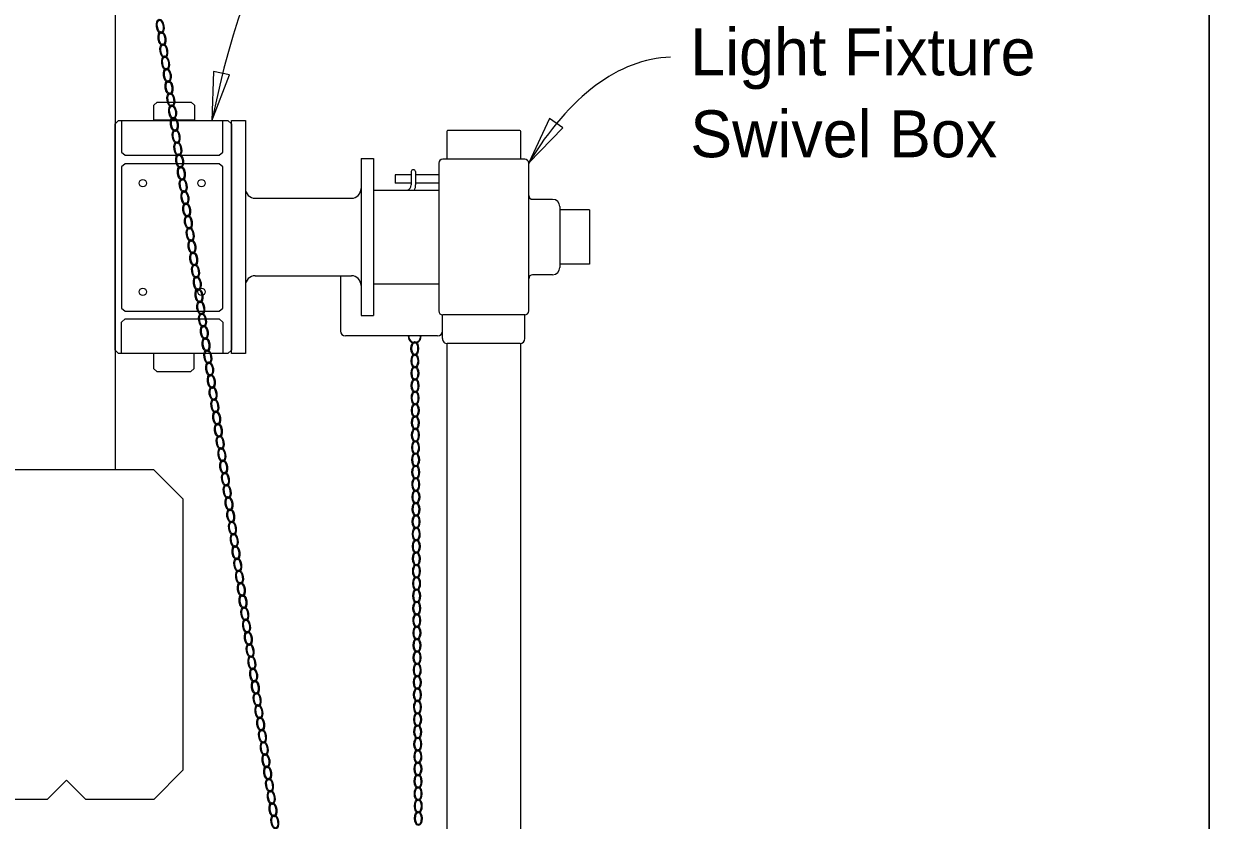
# Model space of a CAD drawing. Extents: x 0 to 20.5, y 0 to 13.
# Drawn here: x 17.979 to 20.525, y 4.722 to 6.433 of the extents above; entities that cross this region are included whole.
import ezdxf

# ---------------------------------------------------------------- set-up
doc = ezdxf.new("R2010")
doc.units = 0
for name, color, linetype in [('ActivePts-ConstElements', 7, 'Continuous'), ('Dimension', 7, 'Continuous'), ('Miscellaneous', 7, 'Continuous'), ('Miscellaneous1', 7, 'Continuous'), ('NavLight', 7, 'Continuous'), ('SupstrConc', 7, 'Continuous'), ('TrafBarrierConc', 7, 'Continuous')]:
    doc.layers.add(name, color=color, linetype=linetype)

msp = doc.modelspace()

# ---------------------------------------------------------------- linework, layer by layer
at = {"layer": 'ActivePts-ConstElements'}
msp.add_lwpolyline([(0, 0), (20.5253, 0), (20.5253, 12.9731), (0, 12.9731)], close=True, dxfattribs=at)
at = {"layer": 'Dimension'}
for points in [[(18.3832, 6.2248), (18.4208, 6.3235), (18.3862, 6.3304)], [(19.0635, 6.1339), (19.1371, 6.2096), (19.1081, 6.2296)]]:
    msp.add_lwpolyline(points, close=True, dxfattribs=at)
for centre, end_param in [((18.9015, 5.6333), 4.215808), ((19.4166, 5.0805), 3.730412)]:
    msp.add_ellipse(centre, major_axis=(0.0485, -1.2809), ratio=0.439724, start_param=3.141585, end_param=end_param, dxfattribs=at)
at = {"layer": 'Miscellaneous'}
for radius, start, end in [(0.0138, 174.5178, 5.4822), (0.0125, 173.952, 6.048)]:
    msp.add_arc((18.8186, 5.761), radius, start, end, dxfattribs=at)
for centre, major_axis, ratio in [((18.2721, 6.4275), (-0.0022, 0.0152), 0.530594), ((18.2721, 6.4275), (-0.0019, 0.0131), 0.458548), ((18.2759, 6.4012), (-0.0022, 0.0152), 0.530594), ((18.2759, 6.4012), (-0.0019, 0.0131), 0.458548), ((18.2797, 6.3749), (-0.0022, 0.0152), 0.530594), ((18.2797, 6.3749), (-0.0019, 0.0131), 0.458548), ((18.2835, 6.3486), (-0.0022, 0.0152), 0.530594), ((18.2835, 6.3486), (-0.0019, 0.0131), 0.458548), ((18.2872, 6.3223), (-0.0022, 0.0152), 0.530594), ((18.2872, 6.3223), (-0.0019, 0.0131), 0.458548), ((18.291, 6.296), (-0.0022, 0.0152), 0.530594), ((18.291, 6.296), (-0.0019, 0.0131), 0.458548), ((18.2948, 6.2697), (-0.0022, 0.0152), 0.530594), ((18.2948, 6.2697), (-0.0019, 0.0131), 0.458548), ((18.2986, 6.2434), (-0.0022, 0.0152), 0.530594), ((18.2986, 6.2434), (-0.0019, 0.0131), 0.458548), ((18.3024, 6.2171), (-0.0022, 0.0152), 0.530594), ((18.3024, 6.2171), (-0.0019, 0.0131), 0.458548), ((18.3062, 6.1908), (-0.0022, 0.0152), 0.530594), ((18.3062, 6.1908), (-0.0019, 0.0131), 0.458548), ((18.3099, 6.1645), (-0.0022, 0.0152), 0.530594), ((18.3099, 6.1645), (-0.0019, 0.0131), 0.458548), ((18.3137, 6.1382), (-0.0022, 0.0152), 0.530594), ((18.3137, 6.1382), (-0.0019, 0.0131), 0.458548), ((18.3175, 6.1119), (-0.0022, 0.0152), 0.530594), ((18.3175, 6.1119), (-0.0019, 0.0131), 0.458548), ((18.3213, 6.0856), (-0.0022, 0.0152), 0.530594), ((18.3213, 6.0856), (-0.0019, 0.0131), 0.458548), ((18.3251, 6.0593), (-0.0022, 0.0152), 0.530594), ((18.3251, 6.0593), (-0.0019, 0.0131), 0.458548), ((18.3289, 6.033), (-0.0022, 0.0152), 0.530594), ((18.3289, 6.033), (-0.0019, 0.0131), 0.458548), ((18.3326, 6.0068), (-0.0022, 0.0152), 0.530594), ((18.3326, 6.0068), (-0.0019, 0.0131), 0.458548), ((18.3364, 5.9805), (-0.0022, 0.0152), 0.530594), ((18.3364, 5.9805), (-0.0019, 0.0131), 0.458548), ((18.3402, 5.9542), (-0.0022, 0.0152), 0.530594), ((18.3402, 5.9542), (-0.0019, 0.0131), 0.458548), ((18.344, 5.9279), (-0.0022, 0.0152), 0.530594), ((18.344, 5.9279), (-0.0019, 0.0131), 0.458548), ((18.3478, 5.9016), (-0.0022, 0.0152), 0.530594), ((18.3478, 5.9016), (-0.0019, 0.0131), 0.458548), ((18.3516, 5.8753), (-0.0022, 0.0152), 0.530594), ((18.3516, 5.8753), (-0.0019, 0.0131), 0.458548), ((18.3553, 5.849), (-0.0022, 0.0152), 0.530594), ((18.3553, 5.849), (-0.0019, 0.0131), 0.458548), ((18.3591, 5.8227), (-0.0022, 0.0152), 0.530594), ((18.3591, 5.8227), (-0.0019, 0.0131), 0.458548), ((18.3629, 5.7964), (-0.0022, 0.0152), 0.530594), ((18.3629, 5.7964), (-0.0019, 0.0131), 0.458548), ((18.3667, 5.7701), (-0.0022, 0.0152), 0.530594), ((18.3667, 5.7701), (-0.0019, 0.0131), 0.458548), ((18.3705, 5.7438), (-0.0022, 0.0152), 0.530594), ((18.3705, 5.7438), (-0.0019, 0.0131), 0.458548), ((18.3743, 5.7175), (-0.0022, 0.0152), 0.530594), ((18.3743, 5.7175), (-0.0019, 0.0131), 0.458548), ((18.8188, 5.7352), (-0.0001, 0.0153), 0.530594), ((18.8188, 5.7352), (-0.0001, 0.0133), 0.458548), ((18.3781, 5.6912), (-0.0022, 0.0152), 0.530594), ((18.3781, 5.6912), (-0.0019, 0.0131), 0.458548), ((18.819, 5.7086), (-0.0001, 0.0153), 0.530594), ((18.819, 5.7086), (-0.0001, 0.0133), 0.458548), ((18.3818, 5.6649), (-0.0022, 0.0152), 0.530594), ((18.8192, 5.6821), (-0.0001, 0.0153), 0.530594), ((18.8192, 5.6821), (-0.0001, 0.0133), 0.458548), ((18.3818, 5.6649), (-0.0019, 0.0131), 0.458548), ((18.3856, 5.6386), (-0.0022, 0.0152), 0.530594), ((18.8194, 5.6555), (-0.0001, 0.0153), 0.530594), ((18.8194, 5.6555), (-0.0001, 0.0133), 0.458548), ((18.3856, 5.6386), (-0.0019, 0.0131), 0.458548), ((18.3894, 5.6123), (-0.0022, 0.0152), 0.530594), ((18.8196, 5.629), (-0.0001, 0.0153), 0.530594), ((18.8196, 5.629), (-0.0001, 0.0133), 0.458548), ((18.3894, 5.6123), (-0.0019, 0.0131), 0.458548), ((18.8198, 5.6024), (-0.0001, 0.0153), 0.530594), ((18.8198, 5.6024), (-0.0001, 0.0133), 0.458548), ((18.3932, 5.586), (-0.0022, 0.0152), 0.530594), ((18.3932, 5.586), (-0.0019, 0.0131), 0.458548), ((18.82, 5.5758), (-0.0001, 0.0153), 0.530594), ((18.82, 5.5758), (-0.0001, 0.0133), 0.458548), ((18.397, 5.5597), (-0.0022, 0.0152), 0.530594), ((18.397, 5.5597), (-0.0019, 0.0131), 0.458548), ((18.8202, 5.5493), (-0.0001, 0.0153), 0.530594), ((18.8202, 5.5493), (-0.0001, 0.0133), 0.458548), ((18.4008, 5.5334), (-0.0022, 0.0152), 0.530594), ((18.4008, 5.5334), (-0.0019, 0.0131), 0.458548), ((18.8204, 5.5227), (-0.0001, 0.0153), 0.530594), ((18.8204, 5.5227), (-0.0001, 0.0133), 0.458548), ((18.4045, 5.5071), (-0.0022, 0.0152), 0.530594), ((18.4045, 5.5071), (-0.0019, 0.0131), 0.458548), ((18.8206, 5.4961), (-0.0001, 0.0153), 0.530594), ((18.8206, 5.4961), (-0.0001, 0.0133), 0.458548), ((18.4083, 5.4808), (-0.0022, 0.0152), 0.530594), ((18.4083, 5.4808), (-0.0019, 0.0131), 0.458548), ((18.8208, 5.4696), (-0.0001, 0.0153), 0.530594), ((18.8208, 5.4696), (-0.0001, 0.0133), 0.458548), ((18.4121, 5.4545), (-0.0022, 0.0152), 0.530594), ((18.4121, 5.4545), (-0.0019, 0.0131), 0.458548), ((18.821, 5.443), (-0.0001, 0.0153), 0.530594), ((18.821, 5.443), (-0.0001, 0.0133), 0.458548), ((18.4159, 5.4282), (-0.0022, 0.0152), 0.530594), ((18.4159, 5.4282), (-0.0019, 0.0131), 0.458548), ((18.8212, 5.4164), (-0.0001, 0.0153), 0.530594), ((18.8212, 5.4164), (-0.0001, 0.0133), 0.458548), ((18.4197, 5.402), (-0.0022, 0.0152), 0.530594), ((18.4197, 5.402), (-0.0019, 0.0131), 0.458548), ((18.8214, 5.3899), (-0.0001, 0.0153), 0.530594), ((18.8214, 5.3899), (-0.0001, 0.0133), 0.458548), ((18.4235, 5.3757), (-0.0022, 0.0152), 0.530594), ((18.4235, 5.3757), (-0.0019, 0.0131), 0.458548), ((18.8216, 5.3633), (-0.0001, 0.0153), 0.530594), ((18.8216, 5.3633), (-0.0001, 0.0133), 0.458548), ((18.4272, 5.3494), (-0.0022, 0.0152), 0.530594), ((18.4272, 5.3494), (-0.0019, 0.0131), 0.458548), ((18.8218, 5.3367), (-0.0001, 0.0153), 0.530594), ((18.8218, 5.3367), (-0.0001, 0.0133), 0.458548), ((18.431, 5.3231), (-0.0022, 0.0152), 0.530594), ((18.431, 5.3231), (-0.0019, 0.0131), 0.458548), ((18.822, 5.3102), (-0.0001, 0.0153), 0.530594), ((18.822, 5.3102), (-0.0001, 0.0133), 0.458548), ((18.4348, 5.2968), (-0.0022, 0.0152), 0.530594), ((18.4348, 5.2968), (-0.0019, 0.0131), 0.458548), ((18.8222, 5.2836), (-0.0001, 0.0153), 0.530594), ((18.8222, 5.2836), (-0.0001, 0.0133), 0.458548), ((18.4386, 5.2705), (-0.0022, 0.0152), 0.530594), ((18.4386, 5.2705), (-0.0019, 0.0131), 0.458548), ((18.8224, 5.257), (-0.0001, 0.0153), 0.530594), ((18.4424, 5.2442), (-0.0022, 0.0152), 0.530594), ((18.4424, 5.2442), (-0.0019, 0.0131), 0.458548), ((18.8226, 5.2305), (-0.0001, 0.0153), 0.530594), ((18.8224, 5.257), (-0.0001, 0.0133), 0.458548), ((18.4462, 5.2179), (-0.0022, 0.0152), 0.530594), ((18.4462, 5.2179), (-0.0019, 0.0131), 0.458548), ((18.8226, 5.2305), (-0.0001, 0.0133), 0.458548), ((18.4499, 5.1916), (-0.0022, 0.0152), 0.530594), ((18.4499, 5.1916), (-0.0019, 0.0131), 0.458548), ((18.8228, 5.2039), (-0.0001, 0.0153), 0.530594), ((18.8228, 5.2039), (-0.0001, 0.0133), 0.458548), ((18.4537, 5.1653), (-0.0022, 0.0152), 0.530594), ((18.4537, 5.1653), (-0.0019, 0.0131), 0.458548), ((18.823, 5.1773), (-0.0001, 0.0153), 0.530594), ((18.823, 5.1773), (-0.0001, 0.0133), 0.458548), ((18.4575, 5.139), (-0.0022, 0.0152), 0.530594), ((18.4575, 5.139), (-0.0019, 0.0131), 0.458548), ((18.8232, 5.1508), (-0.0001, 0.0153), 0.530594), ((18.8232, 5.1508), (-0.0001, 0.0133), 0.458548), ((18.4613, 5.1127), (-0.0022, 0.0152), 0.530594), ((18.4613, 5.1127), (-0.0019, 0.0131), 0.458548), ((18.8234, 5.1242), (-0.0001, 0.0153), 0.530594), ((18.8234, 5.1242), (-0.0001, 0.0133), 0.458548), ((18.4651, 5.0864), (-0.0022, 0.0152), 0.530594), ((18.4651, 5.0864), (-0.0019, 0.0131), 0.458548), ((18.8236, 5.0976), (-0.0001, 0.0153), 0.530594), ((18.8236, 5.0976), (-0.0001, 0.0133), 0.458548), ((18.4689, 5.0601), (-0.0022, 0.0152), 0.530594), ((18.4689, 5.0601), (-0.0019, 0.0131), 0.458548), ((18.8238, 5.0711), (-0.0001, 0.0153), 0.530594), ((18.8238, 5.0711), (-0.0001, 0.0133), 0.458548), ((18.4726, 5.0338), (-0.0022, 0.0152), 0.530594), ((18.4726, 5.0338), (-0.0019, 0.0131), 0.458548), ((18.824, 5.0445), (-0.0001, 0.0153), 0.530594), ((18.824, 5.0445), (-0.0001, 0.0133), 0.458548), ((18.4764, 5.0075), (-0.0022, 0.0152), 0.530594), ((18.4764, 5.0075), (-0.0019, 0.0131), 0.458548), ((18.8242, 5.0179), (-0.0001, 0.0153), 0.530594), ((18.8242, 5.0179), (-0.0001, 0.0133), 0.458548), ((18.4802, 4.9812), (-0.0022, 0.0152), 0.530594), ((18.4802, 4.9812), (-0.0019, 0.0131), 0.458548), ((18.8244, 4.9914), (-0.0001, 0.0153), 0.530594), ((18.8244, 4.9914), (-0.0001, 0.0133), 0.458548), ((18.484, 4.9549), (-0.0022, 0.0152), 0.530594), ((18.484, 4.9549), (-0.0019, 0.0131), 0.458548), ((18.8246, 4.9648), (-0.0001, 0.0153), 0.530594), ((18.8246, 4.9648), (-0.0001, 0.0133), 0.458548), ((18.4878, 4.9286), (-0.0022, 0.0152), 0.530594), ((18.4878, 4.9286), (-0.0019, 0.0131), 0.458548), ((18.8248, 4.9382), (-0.0001, 0.0153), 0.530594), ((18.8248, 4.9382), (-0.0001, 0.0133), 0.458548), ((18.4916, 4.9023), (-0.0022, 0.0152), 0.530594), ((18.4916, 4.9023), (-0.0019, 0.0131), 0.458548), ((18.825, 4.9117), (-0.0001, 0.0153), 0.530594), ((18.825, 4.9117), (-0.0001, 0.0133), 0.458548), ((18.4954, 4.876), (-0.0022, 0.0152), 0.530594), ((18.4954, 4.876), (-0.0019, 0.0131), 0.458548), ((18.8252, 4.8851), (-0.0001, 0.0153), 0.530594), ((18.8252, 4.8851), (-0.0001, 0.0133), 0.458548), ((18.4991, 4.8497), (-0.0022, 0.0152), 0.530594), ((18.8254, 4.8585), (-0.0001, 0.0153), 0.530594), ((18.8254, 4.8585), (-0.0001, 0.0133), 0.458548), ((18.4991, 4.8497), (-0.0019, 0.0131), 0.458548), ((18.5029, 4.8234), (-0.0022, 0.0152), 0.530594), ((18.8256, 4.832), (-0.0001, 0.0153), 0.530594), ((18.8256, 4.832), (-0.0001, 0.0133), 0.458548), ((18.5029, 4.8234), (-0.0019, 0.0131), 0.458548), ((18.5067, 4.7971), (-0.0022, 0.0152), 0.530594), ((18.8258, 4.8054), (-0.0001, 0.0153), 0.530594), ((18.8258, 4.8054), (-0.0001, 0.0133), 0.458548), ((18.5067, 4.7971), (-0.0019, 0.0131), 0.458548), ((18.826, 4.7788), (-0.0001, 0.0153), 0.530594), ((18.826, 4.7788), (-0.0001, 0.0133), 0.458548), ((18.5105, 4.7709), (-0.0022, 0.0152), 0.530594), ((18.5105, 4.7709), (-0.0019, 0.0131), 0.458548), ((18.8262, 4.7523), (-0.0001, 0.0153), 0.530594), ((18.8262, 4.7523), (-0.0001, 0.0133), 0.458548), ((18.5143, 4.7446), (-0.0022, 0.0152), 0.530594), ((18.5143, 4.7446), (-0.0019, 0.0131), 0.458548), ((18.8264, 4.7257), (-0.0001, 0.0153), 0.530594), ((18.8264, 4.7257), (-0.0001, 0.0133), 0.458548), ((18.5181, 4.7183), (-0.0022, 0.0152), 0.530594), ((18.5181, 4.7183), (-0.0019, 0.0131), 0.458548)]:
    msp.add_ellipse(centre, major_axis=major_axis, ratio=ratio, dxfattribs=at)
at = {"layer": 'Miscellaneous1'}
msp.add_lwpolyline([(0, 12.9731), (20.5253, 12.9731), (20.5253, 0), (0, 0)], close=True, dxfattribs=at)
at = {"layer": 'NavLight'}
for p, q in [((18.8875, 6.2015), (18.8875, 6.1421)), ((19.0442, 6.2036), (18.8894, 6.2036)), ((19.0462, 6.2015), (19.0462, 6.1421)), ((18.7035, 6.1435), (18.7035, 5.8064)), ((18.7035, 6.1435), (18.7303, 6.1435)), ((18.7303, 6.1435), (18.7303, 5.8064)), ((19.0549, 6.1421), (18.8788, 6.1421)), ((18.8109, 6.1157), (18.8109, 6.0868)), ((18.8206, 6.1157), (18.8206, 6.0869)), ((18.8703, 6.1335), (18.8703, 5.8163)), ((19.0634, 6.1335), (19.0634, 6.0644)), ((18.7766, 6.1086), (18.7766, 6.0905)), ((18.8109, 6.1086), (18.7766, 6.1086)), ((18.8109, 6.0904), (18.7766, 6.0904)), ((18.8697, 6.1086), (18.8207, 6.1086)), ((18.8704, 6.0904), (18.8207, 6.0904)), ((18.7304, 6.0756), (18.8703, 6.0756)), ((19.0634, 6.0644), (19.0634, 5.8853)), ((18.4758, 6.0582), (18.6827, 6.0582)), ((19.1147, 6.0558), (19.0719, 6.0558)), ((19.1303, 6.0402), (19.1303, 5.9095)), ((19.1941, 6.0331), (19.1302, 6.0331)), ((19.1941, 6.0331), (19.1941, 5.9166)), ((19.1941, 5.9166), (19.1302, 5.9166)), ((18.4758, 5.8916), (18.6827, 5.8916)), ((18.6594, 5.8915), (18.6594, 5.7727)), ((19.0634, 5.8853), (19.0634, 5.8163)), ((19.1147, 5.8939), (19.0719, 5.8939)), ((18.7304, 5.874), (18.8703, 5.874)), ((18.7035, 5.8064), (18.7303, 5.8064)), ((18.8783, 5.7566), (18.8783, 5.8076)), ((19.0554, 5.8078), (18.8788, 5.8078)), ((19.0554, 5.7565), (19.0554, 5.8077)), ((18.8679, 5.7623), (18.6698, 5.7623)), ((18.8877, 5.7461), (18.8877, 3.1215)), ((19.045, 5.7461), (18.8887, 5.7461)), ((19.046, 5.7461), (19.046, 3.1215))]:
    msp.add_line(p, q, dxfattribs=at)
for points in [[(18.2581, 6.2256), (18.2581, 6.2579), (18.2657, 6.2646), (18.3386, 6.2646), (18.346, 6.2579), (18.346, 6.2256)], [(18.425, 6.2184), (18.425, 5.7315), (18.4175, 5.7249), (18.1824, 5.7249), (18.175, 5.7315), (18.175, 6.2184), (18.1824, 6.2249), (18.4175, 6.2249)], [(18.1891, 6.2248), (18.1891, 6.1574), (18.1967, 6.1508), (18.3987, 6.1508), (18.4063, 6.1574), (18.4063, 6.2248)], [(18.4251, 6.2249), (18.455, 6.2249), (18.455, 5.7249), (18.4251, 5.7249)], [(18.1891, 6.1256), (18.1891, 5.8222), (18.1967, 5.8155), (18.3987, 5.8155), (18.4063, 5.8222), (18.4063, 6.1256), (18.3987, 6.1324), (18.1967, 6.1324)], [(18.1891, 5.7248), (18.1891, 5.7922), (18.1967, 5.7989), (18.3987, 5.7989), (18.4063, 5.7922), (18.4063, 5.7248)], [(18.2573, 5.7249), (18.2573, 5.6925), (18.2648, 5.6859), (18.3376, 5.6859), (18.3452, 5.6925), (18.3452, 5.7249)]]:
    msp.add_lwpolyline(points, close=True, dxfattribs=at)
for centre in [(18.2348, 6.0905), (18.3607, 6.0905), (18.2348, 5.8572), (18.3607, 5.8572)]:
    msp.add_circle(centre, 0.00794, dxfattribs=at)
for centre, radius, start, end in [((18.8896, 6.2015), 0.00201, 90, 180), ((19.0443, 6.2015), 0.00201, 0, 90), ((18.879, 6.1335), 0.00854, 90, 180), ((19.055, 6.1335), 0.00854, 0, 90), ((18.8158, 6.1144), 0.00502, 14.7371, 165.2629), ((18.8005, 6.0859), 0.0104, 279.3886, 4.8828), ((18.8005, 6.0859), 0.0202, 329.3017, 2.6969), ((18.4759, 6.079), 0.0208, 180, 270), ((18.6827, 6.079), 0.0208, 270, 360), ((19.0721, 6.0644), 0.00854, 180, 270), ((19.1147, 6.0402), 0.0156, 0, 90), ((19.1147, 5.9095), 0.0156, 270, 0), ((18.4759, 5.8708), 0.0208, 90, 180), ((18.6827, 5.8708), 0.0208, 0, 90), ((19.0721, 5.8853), 0.00854, 90, 180), ((18.879, 5.8162), 0.00854, 180, 270), ((19.055, 5.8162), 0.00854, 270, 0), ((18.6698, 5.7727), 0.0104, 180, 270), ((18.8679, 5.7727), 0.0104, 270.0013, 0), ((18.8887, 5.7565), 0.0104, 179.9813, 270), ((19.045, 5.7565), 0.0104, 270, 0)]:
    msp.add_arc(centre, radius, start, end, dxfattribs=at)
at = {"layer": 'SupstrConc'}
for p, q in [((18.2584, 5.4749), (15.7675, 5.4749)), ((18.2584, 5.4749), (18.3209, 5.4124)), ((18.3209, 5.4124), (18.3208, 4.8291)), ((18.3208, 4.8291), (18.2583, 4.7666)), ((18.0708, 4.8082), (18.0292, 4.7666)), ((18.0708, 4.8082), (18.1125, 4.7666)), ((18.0292, 4.7666), (15.7675, 4.7666)), ((18.2583, 4.7666), (18.1125, 4.7666))]:
    msp.add_line(p, q, dxfattribs=at)
at = {"layer": 'TrafBarrierConc'}
msp.add_line((18.175, 7.3498), (18.175, 5.4749), dxfattribs=at)

# ---------------------------------------------------------------- texts
at = {"layer": 'Dimension'}
for s, p in [('Light Fixture', (19.4105, 6.3222)), ('Swivel Box', (19.4105, 6.1462))]:
    msp.add_text(s, height=0.1008, dxfattribs=at).set_placement(p)

doc.saveas('drawing.dxf')
